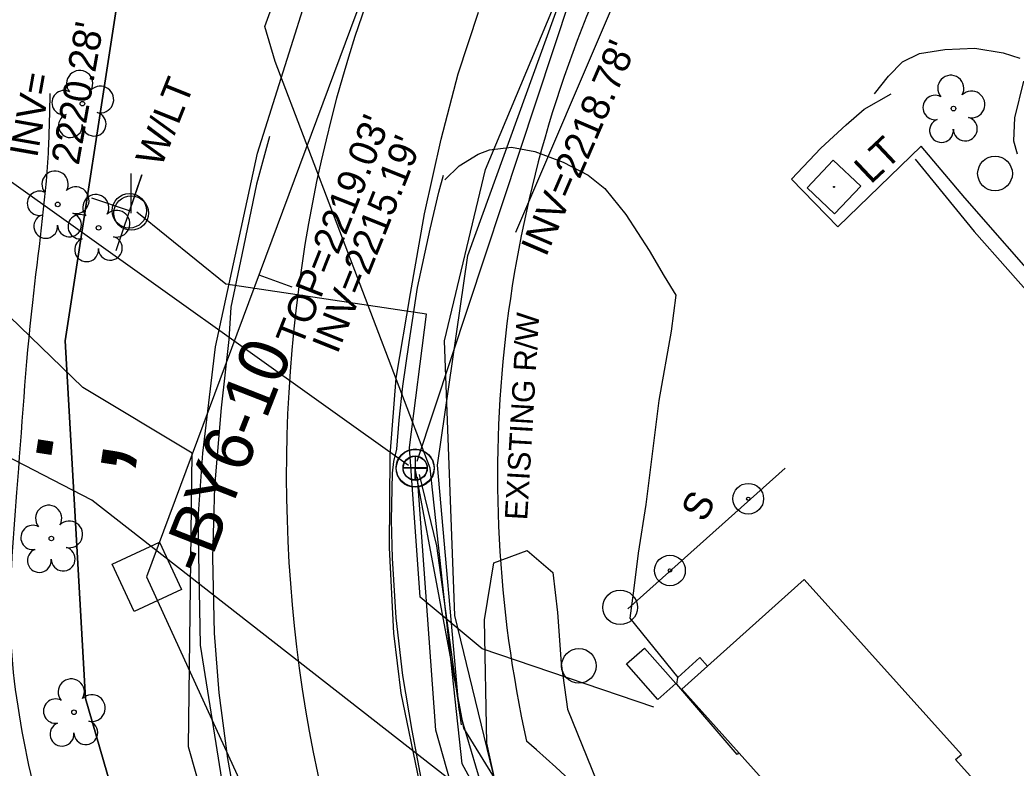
# Model space of a CAD drawing. Extents: x 945964 to 948456, y 631061 to 636061.
# Drawn here: x 947347.7 to 947489.3, y 634284.5 to 634390.9 of the extents above; entities that cross this region are included whole.
import ezdxf

# ---------------------------------------------------------------- set-up
doc = ezdxf.new("R2010")
doc.units = 0
for name, color, linetype in [('CTL Supplemental Horizontal and Vertical CELL', 7, 'Continuous'), ('Exist Building', 7, 'Continuous'), ('Exist Horizontal Alignment', 7, 'Continuous'), ('Exist Horizontal Baseline Alignment', 7, 'Continuous'), ('Exist Horizontal Baseline Alignment Station Label', 7, 'Continuous'), ('Exist Horizontal Baseline Alignment Tick small', 7, 'Continuous'), ('Exist Other Culture Area Outline', 7, 'Continuous'), ('Exist Other Culture Fence Line', 7, 'Continuous'), ('Exist Other Culture Sign CELL', 7, 'Continuous'), ('Exist Other Culture Sign Text', 7, 'Continuous'), ('Exist Right of Way Control of Access CA Symbol CELL', 7, 'Continuous'), ('Exist Right of Way Control of Access Line', 7, 'Continuous'), ('Exist Right of Way Line', 7, 'Continuous'), ('Exist Right of Way Line Text', 7, 'Continuous'), ('Exist Roads Curbs', 7, 'Continuous'), ('Exist Roads EOP', 7, 'Continuous'), ('Exist Roads EOP Other', 7, 'Continuous'), ('Exist Roads EOT', 7, 'Continuous'), ('Exist Structure Minor Pipes RCP 15 Inch', 7, 'Continuous'), ('Exist Structure Minor Pipes RCP 15 Inch Invert', 7, 'Continuous'), ('Exist Utilities Gas UG Line SUE', 7, 'Continuous'), ('Exist Utilities Other Pole CELL', 7, 'Continuous'), ('Exist Utilities Other Pole With Base CELL', 7, 'Continuous'), ('Exist Utilities Other Pole With Base Text', 7, 'Continuous'), ('Exist Utilities Power Joint Use Telephone CELL', 7, 'Continuous'), ('Exist Utilities Power Joint Use Telephone Text', 7, 'Continuous'), ('Exist Utilities Power Pole CELL', 7, 'Continuous'), ('Exist Utilities Sanitary Sewer Forced Main SUE', 7, 'Continuous'), ('Exist Utilities Sanitary Sewer Manhole CELL', 7, 'Continuous'), ('Exist Utilities Sanitary Sewer Manhole Text', 7, 'Continuous'), ('Exist Utilities Sanitary Sewer UG Line', 7, 'Continuous'), ('Exist Utilities Sanitary Sewer UG Line Invert Elevation', 7, 'Continuous'), ('Exist Utilities Telephone UG Cable SUE', 7, 'Continuous'), ('Exist Utilities TV UG Cable SUE', 7, 'Continuous'), ('Exist Utilities Water UG Line SUE', 7, 'Continuous'), ('Exist Vegetation Hedge Row', 7, 'Continuous'), ('Exist Vegetation Tree CELL', 7, 'Continuous')]:
    doc.layers.add(name, color=color, linetype=linetype)

# ---------------------------------------------------------------- blocks, each defined once
blk = doc.blocks.new('EXIST UTILITIES POWER JOINT USE TELEPHONE')
at = {"layer": 'Exist Utilities Power Joint Use Telephone CELL'}
blk.add_line((0, 0), (0, 0), dxfattribs=at)
blk.add_lwpolyline([(-0.1188, 0), (0.108, -0.0008), (0, -0.0004), (0, 0.1125)], dxfattribs=at)
blk.add_circle((0, 0.0001), 0.049, dxfattribs=at)
blk = doc.blocks.new('EXIST UTILITIES OTHER POLE')
at = {"layer": 'Exist Utilities Other Pole CELL'}
blk.add_circle((0, 0), 0.0493, dxfattribs=at)
blk = doc.blocks.new('CTL SUPPLEMENTAL HORIZONTAL AND VERTICAL')
at = {"layer": 'CTL Supplemental Horizontal and Vertical CELL'}
blk.add_line((0, 0), (0, 0), dxfattribs=at)
blk.add_lwpolyline([(-0.0735, 0.074), (0.07475, 0.074), (0.07475, -0.0745), (-0.0735, -0.0745)], close=True, dxfattribs=at)

msp = doc.modelspace()

# ---------------------------------------------------------------- linework, layer by layer
at = {"layer": 'Exist Building'}
msp.add_lwpolyline([(947510.33, 634252.68), (947480.67, 634285.75), (947481.48, 634286.47), (947459.16, 634311.35), (947441.75, 634295.74), (947464.96, 634269.86), (947465.42, 634270.28), (947496.9, 634235.09), (947503.25, 634240.77), (947500.47, 634243.89), (947502.59, 634245.78), (947510.27, 634237.18), (947515.93, 634242.23), (947508.25, 634250.82)], close=True, dxfattribs=at)
at = {"layer": 'Exist Horizontal Alignment'}
msp.add_arc((947590.22, 634326.11), 204.63, 154.4793, 209.0487, dxfattribs=at)
at = {"layer": 'Exist Horizontal Baseline Alignment'}
for p, q in [((947475.75, 634607.69), (947365.74, 634311.71)), ((947365.74, 634311.71), (947471.88, 634079.79))]:
    msp.add_line(p, q, dxfattribs=at)
at = {"layer": 'Exist Horizontal Baseline Alignment Tick small'}
msp.add_line((947381.7, 634354.66), (947386.39, 634352.92), dxfattribs=at)
at = {"layer": 'Exist Other Culture Area Outline'}
msp.add_lwpolyline([(947438.36, 634294.3), (947433.91, 634299.35), (947436.46, 634301.6), (947440.91, 634296.55)], close=True, dxfattribs=at)
msp.add_lwpolyline([(947449.84, 634286.71), (947449.61, 634286.48), (947441.06, 634296.48), (947441.22, 634297.41)], dxfattribs=at)
for points in [[(947502.74, 633551.84), (947491.43, 633598.35), (947481.81, 633655.47), (947473.42, 633706.38), (947465.97, 633751.69), (947457.82, 633800.26), (947449.82, 633849.21), (947440.92, 633903.16), (947434.15, 633943.61), (947423.94, 634005.84), (947416.66, 634047.81), (947408.17, 634100.43), (947401.63, 634128.51), (947390.02, 634166.53), (947375.97, 634204.38), (947358.86, 634250.48), (947349.29, 634283.79), (947346.49, 634302.94), (947347.33, 634323.73), (947349.56, 634350.73), (947351.79, 634371.96), (947352.04, 634380.41)], [(947498.1, 633549.11), (947485.93, 633597.25), (947475.95, 633654.8), (947467.52, 633705.53), (947460.23, 633750.52), (947452.1, 633799.7), (947443.77, 633849.62), (947435.12, 633902.3), (947428.36, 633943.07), (947418.1, 634004.56), (947410.76, 634048.74), (947402.29, 634099.82), (947395.78, 634127.82), (947384.42, 634164.9), (947370.55, 634202.66), (947354.33, 634246.12), (947343.66, 634281.62), (947340.62, 634293.86), (947329.49, 634297.96), (947319.27, 634301.42)]]:
    msp.add_spline(points, degree=3, dxfattribs=at)
at = {"layer": 'Exist Other Culture Fence Line'}
msp.add_lwpolyline([(947361.98, 634396.08), (947354.16, 634345.29), (947357.06, 634294.45), (947370.3, 634248.64), (947405.27, 634177.07), (947440.28, 634105.16), (947495.56, 633990.52)], dxfattribs=at)
at = {"layer": 'Exist Other Culture Sign CELL'}
msp.add_line((947456.46, 634327.19), (947434.09, 634307.19), dxfattribs=at)
for centre, radius in [((947451.21, 634322.83), 2.18), ((947451.21, 634322.83), 0.24), ((947440.09, 634312.63), 2.18), ((947440.09, 634312.63), 0.24)]:
    msp.add_circle(centre, radius, dxfattribs=at)
at = {"layer": 'Exist Right of Way Control of Access CA Symbol CELL'}
msp.add_line((947354.87, 634334.35), (947354.87, 634334.35), dxfattribs=at)
at = {"layer": 'Exist Right of Way Control of Access Line'}
for points in [[(947354.16, 634345.29), (947361.98, 634396.08)], [(947357.06, 634294.45), (947354.16, 634345.29)], [(947370.3, 634248.64), (947357.06, 634294.45)]]:
    msp.add_lwpolyline(points, dxfattribs=at)
at = {"layer": 'Exist Right of Way Line'}
for centre, radius, start, end in [((947590.22, 634326.11), 174.63, 154.4793, 192.484), ((947283.18, 634130.06), 209.05, 17.0534, 49.2199)]:
    msp.add_arc(centre, radius, start, end, dxfattribs=at)
at = {"layer": 'Exist Roads Curbs'}
msp.add_lwpolyline([(947585.46, 634247.07), (947576.8, 634256.87), (947566.08, 634269.1), (947558.11, 634278.14), (947544.18, 634294.06), (947530.56, 634309.66), (947517.42, 634324.9), (947507.14, 634336.62), (947493.68, 634352.24), (947481.98, 634365.6), (947475.79, 634372.93), (947463.92, 634361.46), (947457.37, 634368.23), (947461.5, 634372.67), (947465.14, 634375.98), (947467.69, 634378.21), (947471.52, 634380.35)], dxfattribs=at)
at = {"layer": 'Exist Roads EOP'}
for points in [[(947421, 634183.62), (947406.27, 634209.93), (947401.98, 634216.83), (947395.94, 634226.9), (947388.58, 634243.25), (947380.28, 634265.79), (947377.16, 634278.52), (947373.4, 634302), (947373.07, 634320.02), (947373.74, 634329.29), (947375.51, 634344.4), (947381.48, 634371.95), (947393.02, 634408.46)], [(947451.1, 634179.34), (947448.97, 634183.64), (947435.79, 634207.87), (947425.09, 634228.88), (947418.71, 634241.92), (947413.45, 634253.5), (947407.82, 634267.67), (947404.5, 634282.57), (947401.92, 634295.17), (947400.88, 634303.73), (947400.25, 634315.87), (947400.33, 634329.02), (947401.21, 634339.97), (947403.23, 634352), (947405.21, 634363.32), (947407.58, 634373.93), (947409.98, 634383.21), (947412.91, 634391.97)], [(947406.01, 634361.15), (947407.25, 634366.41), (947407.93, 634368.81)], [(947405.08, 634281.36), (947403.45, 634289.9), (947403.45, 634289.9), (947402.14, 634297.72), (947402.14, 634297.72), (947401.2, 634305.88), (947401.2, 634305.88), (947400.65, 634314.4), (947400.65, 634314.4), (947400.54, 634319.78), (947400.54, 634319.78), (947400.66, 634326.47), (947400.66, 634326.47), (947400.84, 634328.1), (947401.27, 634329.89), (947401.61, 634333.97), (947401.61, 634333.97), (947402.16, 634338.84), (947402.16, 634338.84), (947403.03, 634345.01), (947403.03, 634345.01), (947404.22, 634352.84), (947406.01, 634361.15)]]:
    msp.add_lwpolyline(points, dxfattribs=at)
at = {"layer": 'Exist Roads EOP Other'}
for points in [[(947469.16, 634380.37), (947471.15, 634382.9), (947473.14, 634384.93), (947475.53, 634386.1), (947479.11, 634386.69), (947483.38, 634386.84), (947487.4, 634386.21), (947489.81, 634385.43)], [(947490.33, 634382.16), (947489.04, 634376.97), (947488.91, 634373.68), (947489.39, 634371.83)], [(947408.09, 634368.16), (947410.14, 634370.14), (947412.85, 634371.81), (947414.43, 634372.43), (947417.58, 634372.78), (947420.87, 634372.2), (947424.93, 634370.67), (947428.49, 634368.83), (947430.85, 634366.91), (947433.82, 634363.21), (947437.11, 634358.12), (947439.25, 634354.47), (947440.94, 634351.75), (947440.26, 634346.63), (947438.51, 634336.8), (947436.66, 634322.03), (947435.58, 634315.1), (947434.97, 634310.13), (947434.41, 634305.87), (947441.22, 634297.41), (947444.34, 634300.28), (947445.44, 634299.05)], [(947474.9, 634371.09), (947483.3, 634360.83), (947492.85, 634349.99), (947500.43, 634341.18), (947513.36, 634326.35), (947527.91, 634309.6), (947541.78, 634293.55), (947555.76, 634277.64), (947567.38, 634264.34), (947578.03, 634252.2), (947584.34, 634244.96)]]:
    msp.add_lwpolyline(points, dxfattribs=at)
at = {"layer": 'Exist Roads EOT'}
msp.add_lwpolyline([(947383.18, 634374.32), (947381.37, 634367.53), (947379.27, 634357.48), (947377.71, 634350.07), (947377.44, 634345.46), (947376.35, 634335.74), (947375.37, 634324.53), (947375.11, 634314.47), (947375.34, 634303.7), (947376.02, 634295.22), (947377.24, 634285.92), (947378.56, 634278.54), (947382.12, 634266.72), (947387.06, 634253.75), (947391.84, 634242.48), (947399.33, 634227.01), (947408.36, 634209.89), (947413.71, 634199.81), (947417.81, 634192.77)], dxfattribs=at)
at = {"layer": 'Exist Structure Minor Pipes RCP 15 Inch'}
msp.add_line((947475.38, 634494.41), (947418.14, 634360.67), dxfattribs=at)
at = {"layer": 'Exist Utilities Gas UG Line SUE'}
for points in [[(947612.33, 633940.05), (947575.73, 633976.97), (947546.11, 634010.49), (947527.86, 634033.53), (947510.62, 634069.53), (947472.03, 634147.29), (947433.42, 634219.72), (947418.22, 634254.28), (947411.73, 634280.58), (947357.94, 634322.64), (947326.51, 634338.86), (947301.56, 634359.84), (947276.46, 634402.07), (947285.91, 634450.24), (947282.53, 634458.27)], [(947612.51, 633955.79), (947586.11, 633987.04), (947559.14, 634026.5), (947535.72, 634037.08), (947515.42, 634068.64), (947474.84, 634149.39), (947438.62, 634222.41), (947421.15, 634255.7), (947410.14, 634292.82), (947407.07, 634327.58), (947411.39, 634357.39), (947432.81, 634416.73)]]:
    msp.add_lwpolyline(points, dxfattribs=at)
at = {"layer": 'Exist Utilities Other Pole CELL'}
for centre in [(947433, 634307.39), (947427.16, 634299.07)]:
    msp.add_circle(centre, 2.46, dxfattribs=at)
at = {"layer": 'Exist Utilities Other Pole With Base CELL'}
msp.add_line((947463.39, 634367.15), (947463.39, 634367.15), dxfattribs=at)
msp.add_lwpolyline([(947459.56, 634367.03), (947463.28, 634370.95), (947467.19, 634367.23), (947463.47, 634363.31), (947459.56, 634367.03)], dxfattribs=at)
msp.add_circle((947463.39, 634367.15), 0.0707, dxfattribs=at)
at = {"layer": 'Exist Utilities Power Pole CELL'}
for q in [(947363.55, 634369.05), (947363.55, 634363.43)]:
    msp.add_line((947363.55, 634363.43), q, dxfattribs=at)
msp.add_circle((947363.55, 634363.43), 2.45, dxfattribs=at)
at = {"layer": 'Exist Utilities Sanitary Sewer Forced Main SUE'}
for points in [[(947592.11, 633966.45), (947577.84, 633979.92), (947531.81, 634035.03), (947512.92, 634068.28), (947487.05, 634150.03), (947453.54, 634225.48), (947431.02, 634257.45), (947410.82, 634290.23), (947403.9, 634327.15)], [(947592.11, 633966.45), (947577.84, 633979.92), (947531.81, 634035.03), (947512.92, 634068.28), (947487.05, 634150.03), (947453.54, 634225.48), (947431.02, 634257.45), (947410.82, 634290.23), (947403.9, 634327.15)], [(947609.68, 633952.75), (947579.78, 633982.12), (947549.67, 634013.59), (947532.94, 634035.86), (947514.88, 634068.47), (947472.66, 634147.58), (947434.5, 634220.3), (947416.99, 634253.85), (947406.82, 634289.94), (947404.24, 634325.88)], [(947410.49, 634290.69), (947406.98, 634316.15), (947404.52, 634326.28)]]:
    msp.add_lwpolyline(points, dxfattribs=at)
at = {"layer": 'Exist Utilities Sanitary Sewer Manhole CELL'}
for points in [[(947403.88, 634328.92), (947403.88, 634325.49), (947403.88, 634327.21), (947405.59, 634327.21), (947402.17, 634327.21)], [(947403.9, 634328.86), (947403.9, 634325.43), (947403.9, 634327.15), (947405.61, 634327.15), (947402.19, 634327.15)]]:
    msp.add_lwpolyline(points, dxfattribs=at)
for centre, radius in [((947403.88, 634327.21), 2.69), ((947403.9, 634327.15), 2.69), ((947403.88, 634327.21), 1.71), ((947403.9, 634327.15), 1.71)]:
    msp.add_circle(centre, radius, dxfattribs=at)
at = {"layer": 'Exist Utilities Sanitary Sewer UG Line'}
for p, q in [((947402.94, 634327.54), (947234.33, 634447.89)), ((947439.98, 634436.33), (947404.12, 634328.12))]:
    msp.add_line(p, q, dxfattribs=at)
at = {"layer": 'Exist Utilities Telephone UG Cable SUE'}
for points in [[(947605.36, 633964.96), (947576.28, 633993.97), (947553.01, 634020.31), (947532.77, 634037.25), (947507.69, 634083.27), (947485.34, 634127.28), (947436.98, 634221.11), (947422.48, 634252.85), (947409.52, 634306.22), (947408.05, 634345.28), (947413.87, 634369.61), (947433.57, 634416.72)], [(947437.79, 634293.19), (947413.4, 634301.48), (947404.59, 634308.83), (947403.1, 634330.12), (947405.51, 634349.08), (947376.98, 634353.3), (947364.37, 634363.55)]]:
    msp.add_lwpolyline(points, dxfattribs=at)
at = {"layer": 'Exist Utilities TV UG Cable SUE'}
msp.add_lwpolyline([(947613, 633956.45), (947585.48, 633982.3), (947553.66, 634018.57), (947532.33, 634035.44), (947513.66, 634068.24), (947471.12, 634146.7), (947433.94, 634220.1), (947419.54, 634254.97), (947421.64, 634264.86), (947410.59, 634285.17), (947406.01, 634327.18), (947384.01, 634384.99), (947382.54, 634389.92), (947399.72, 634437.38)], dxfattribs=at)
at = {"layer": 'Exist Utilities Water UG Line SUE'}
for points in [[(947372.22, 634329.29), (947356.68, 634338.64), (947332.8, 634361.72)], [(947570.82, 633950.23), (947545.89, 633976.92), (947525.57, 634000.75), (947503.54, 634032.3), (947484.86, 634064.9), (947447.11, 634131.53), (947402.42, 634210.63), (947379.77, 634259.03), (947371.68, 634287.56), (947372.22, 634329.29)]]:
    msp.add_lwpolyline(points, dxfattribs=at)
at = {"layer": 'Exist Vegetation Hedge Row'}
msp.add_lwpolyline([(947448.95, 634211.6), (947440.05, 634223.24), (947429.25, 634242.33), (947422.39, 634254.95), (947418.17, 634269.26), (947414.09, 634288.1), (947413.73, 634305.62), (947415.06, 634313.71), (947419.82, 634315.49), (947423.46, 634312.35), (947424.09, 634306.64), (947424.64, 634299.39), (947425.52, 634292.93), (947429.68, 634282.62), (947434.79, 634274.14), (947440.93, 634267.53), (947449.21, 634259.09), (947456.17, 634254.1)], dxfattribs=at)
at = {"layer": 'Exist Vegetation Tree CELL'}
for p, q in [((947356.62, 634378.97), (947356.62, 634378.97)), ((947480.37, 634378.28), (947480.37, 634378.28)), ((947353.12, 634364.66), (947353.12, 634364.66)), ((947358.92, 634361.33), (947358.92, 634361.33)), ((947352.21, 634317.17), (947352.21, 634317.17)), ((947355.43, 634292.48), (947355.43, 634292.48))]:
    msp.add_line(p, q, dxfattribs=at)
for centre in [(947356.62, 634378.97), (947480.37, 634378.28), (947353.12, 634364.66), (947358.92, 634361.33), (947352.21, 634317.17), (947355.43, 634292.48)]:
    msp.add_circle(centre, 0.326, dxfattribs=at)
for centre, radius, start, end in [((947356.24, 634381.84), 1.86, 330.1651, 219.7134), ((947479.98, 634381.15), 1.86, 330.1651, 219.7134), ((947354.02, 634379.12), 1.73, 62.6636, 279.3457), ((947359.17, 634379.56), 1.9, 257.1011, 134.1999), ((947482.92, 634378.86), 1.9, 257.1011, 134.1999), ((947477.76, 634378.43), 1.73, 62.6636, 279.3457), ((947354.92, 634375.85), 1.69, 111.5671, 6.231), ((947358.29, 634376.07), 1.7, 181.2822, 74.56), ((947478.66, 634375.16), 1.69, 111.5671, 6.231), ((947482.04, 634375.38), 1.7, 181.2822, 74.56), ((947352.74, 634367.54), 1.86, 330.1651, 219.7134), ((947350.52, 634364.82), 1.73, 62.6636, 279.3457), ((947355.67, 634365.25), 1.9, 257.1011, 134.1999), ((947358.53, 634364.2), 1.86, 330.1651, 219.7134), ((947354.79, 634361.76), 1.7, 181.2822, 74.56), ((947361.47, 634361.92), 1.9, 257.1011, 134.1999), ((947351.42, 634361.54), 1.69, 111.5671, 6.231), ((947356.31, 634361.48), 1.73, 62.6636, 279.3457), ((947357.21, 634358.21), 1.69, 111.5671, 6.231), ((947360.59, 634358.43), 1.7, 181.2822, 74.56), ((947351.83, 634320.04), 1.86, 330.1651, 219.7134), ((947354.76, 634317.76), 1.9, 257.1011, 134.1999), ((947349.61, 634317.32), 1.73, 62.6636, 279.3457), ((947350.51, 634314.05), 1.69, 111.5671, 6.231), ((947353.89, 634314.27), 1.7, 181.2822, 74.56), ((947355.04, 634295.36), 1.86, 330.1651, 219.7134), ((947352.82, 634292.64), 1.73, 62.6636, 279.3457), ((947357.97, 634293.07), 1.9, 257.1011, 134.1999), ((947357.1, 634289.58), 1.7, 181.2822, 74.56), ((947353.72, 634289.36), 1.69, 111.5671, 6.231)]:
    msp.add_arc(centre, radius, start, end, dxfattribs=at)

# ---------------------------------------------------------------- block references
at = {"layer": 'CTL Supplemental Horizontal and Vertical CELL', "xscale": 50, "yscale": 50, "rotation": 25.077408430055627}
msp.add_blockref('CTL SUPPLEMENTAL HORIZONTAL AND VERTICAL', (947365.74, 634311.71), dxfattribs=at)
at = {"layer": 'Exist Utilities Other Pole CELL', "xscale": 50, "yscale": 50}
msp.add_blockref('EXIST UTILITIES OTHER POLE', (947486.26, 634369.04), dxfattribs=at)
at = {"layer": 'Exist Utilities Power Joint Use Telephone CELL', "xscale": 49.99999999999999, "yscale": 50.00000000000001, "rotation": 71.48139379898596}
msp.add_blockref('EXIST UTILITIES POWER JOINT USE TELEPHONE', (947363.3, 634363.75), dxfattribs=at)

# ---------------------------------------------------------------- texts
at = {"layer": 'Exist Horizontal Baseline Alignment Station Label'}
msp.add_text('-BY6-10', height=7, rotation=68.5783, dxfattribs=at).set_placement((947373.99, 634311.7))
at = {"layer": 'Exist Other Culture Sign Text'}
msp.add_text('S', height=4, rotation=60.9356, dxfattribs=at).set_placement((947444.96, 634319.31))
at = {"layer": 'Exist Right of Way Control of Access CA Symbol CELL'}
msp.add_text(';', height=15, rotation=81.2486, dxfattribs=at).set_placement((947361.15, 634325.79))
at = {"layer": 'Exist Right of Way Line Text'}
msp.add_text('EXISTING R/W', height=3.2, rotation=86.6393, dxfattribs=at).set_placement((947419.8, 634319.73))
at = {"layer": 'Exist Structure Minor Pipes RCP 15 Inch Invert'}
for s, rotation, p in [("2220.28'", 79.9682, (947356.1, 634370.12)), ("INV=2218.78'", 66.6808, (947422.47, 634357.06)), ('INV=', 79.9682, (947350.19, 634371.17))]:
    msp.add_text(s, height=4, rotation=rotation, dxfattribs=at).set_placement(p)
at = {"layer": 'Exist Utilities Other Pole With Base Text'}
msp.add_text('LT', height=4, rotation=43.2804, dxfattribs=at).set_placement((947468.61, 634367.43))
at = {"layer": 'Exist Utilities Power Joint Use Telephone Text'}
msp.add_text('W/LT', height=4, rotation=68.1894, dxfattribs=at).set_placement((947367.8, 634369.76))
at = {"layer": 'Exist Utilities Sanitary Sewer Manhole Text'}
msp.add_text("TOP=2219.03'", height=4, rotation=68.4524, dxfattribs=at).set_placement((947387.74, 634344.24))
at = {"layer": 'Exist Utilities Sanitary Sewer UG Line Invert Elevation'}
msp.add_text("INV=2215.19'", height=4, rotation=68.1849, dxfattribs=at).set_placement((947392.84, 634343.27))

doc.saveas('drawing.dxf')
